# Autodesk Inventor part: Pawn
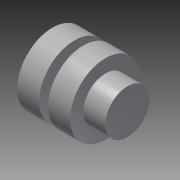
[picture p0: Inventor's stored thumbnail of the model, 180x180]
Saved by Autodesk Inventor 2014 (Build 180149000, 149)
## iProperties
Created: 2006-03
Part Number: Pawn
Document SubType Name: Modeling
Designer: debonom
Material: Stainless Steel, 440C
Mass: 19.8431 g
Surface Area: 13.6973 cm^2
Volume: 2.5604 cm^3
Density: 7.75 g/cm^3
Appearance: Steel
Author: debonom
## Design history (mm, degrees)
sketch "Sketch1"
  geometry: L1 (0, 0)-(5, 0); L2 (5, 0)-(5, 5); L3 (5, 5)-(0, 5); L4 (0, 5)-(0, 0); L5 (5, 8)-(10, 8); L6 (10, 8)-(10, 0); L7 (10, 0)-(5, 0); L8 (5, 0)-(5, 8); L9 (10, 5)-(12, 5); L10 (12, 5)-(12, 0); L11 (12, 0)-(10, 0); L12 (10, 0)-(10, 5); L13 (-3.4, 0)-(20.4, 0) reference; L14 (12, 8)-(17, 8); L15 (17, 8)-(17, 0); L16 (17, 0)-(12, 0); L17 (12, 0)-(12, 8)
  constraints: 32 end point, 8 parallel, 7 collinear, 4 horizontal, 4 perpendicular, 1 point on line
  dimensions: "d0" = 5 distance of L2.end L3.end; "d1" = 5 distance of L3.end L1.start; "d2" = 8 distance between parallel lines of L13 L5; "d3" = 2 distance of L9.start L9.end; "d4" = 5 distance of L14.start L14.end; "d5" = 5 distance between parallel lines of L9 L13
revolve "Revolution1" sketch "Sketch1" stored, may be unused: angle "d6" = 90 deg
body "Solid1"
